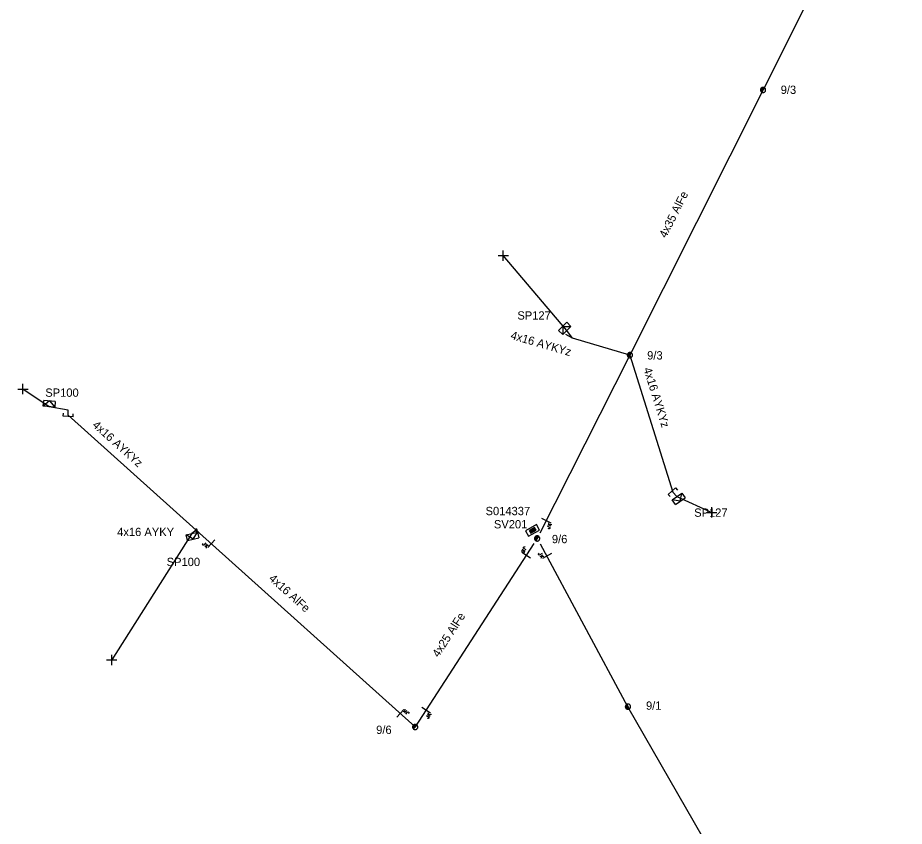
# Model space of a CAD drawing. Extents: x -717562 to -713845, y -1151196 to -1143903.
# Drawn here: x -714702.4 to -714595.8, y -1145677.8 to -1145580.5 of the extents above; entities that cross this region are included whole.
import ezdxf

# ---------------------------------------------------------------- set-up
doc = ezdxf.new("R2010")
doc.units = 0
for name, color, linetype in [('Vrstva 1', 7, 'Continuous'), ('Vrstva 12', 7, 'Continuous'), ('Vrstva 13', 7, 'Continuous'), ('Vrstva 15', 7, 'Continuous'), ('Vrstva 18', 7, 'Continuous'), ('Vrstva 2', 7, 'Continuous'), ('Vrstva 28', 7, 'Continuous'), ('Vrstva 29', 7, 'Continuous'), ('Vrstva 30', 7, 'Continuous'), ('Vrstva 31', 7, 'Continuous'), ('Vrstva 33', 7, 'Continuous'), ('Vrstva 34', 7, 'Continuous'), ('Vrstva 52', 7, 'Continuous'), ('Vrstva 54', 7, 'Continuous'), ('Vrstva 55', 7, 'Continuous'), ('Vrstva 59', 7, 'Continuous'), ('Vrstva 8', 7, 'Continuous'), ('Vrstva 9', 7, 'Continuous')]:
    doc.layers.add(name, color=color, linetype=linetype)

# ---------------------------------------------------------------- blocks, each defined once
blk = doc.blocks.new('NN440')
at = {"layer": 'Vrstva 2'}
for points in [[(0.63, 0), (0.63, 0.06), (0.62, 0.13), (0.6, 0.19), (0.58, 0.25), (0.55, 0.31), (0.51, 0.37), (0.47, 0.42), (0.42, 0.46), (0.37, 0.51), (0.32, 0.54), (0.26, 0.57), (0.2, 0.59), (0.13, 0.61), (0.07, 0.62), (0, 0.63), (-0.06, 0.62), (-0.13, 0.61), (-0.19, 0.59), (-0.26, 0.57), (-0.31, 0.54), (-0.37, 0.51), (-0.42, 0.46), (-0.47, 0.42), (-0.51, 0.37), (-0.54, 0.31), (-0.57, 0.25), (-0.6, 0.19), (-0.62, 0.13), (-0.63, 0.06), (-0.63, 0), (-0.63, -0.07), (-0.62, -0.14), (-0.6, -0.2), (-0.57, -0.26), (-0.54, -0.32), (-0.51, -0.37), (-0.47, -0.43), (-0.42, -0.47), (-0.37, -0.51), (-0.31, -0.55), (-0.26, -0.58), (-0.19, -0.6), (-0.13, -0.62), (-0.06, -0.63), (0, -0.63), (0.07, -0.63), (0.13, -0.62), (0.2, -0.6), (0.26, -0.58), (0.32, -0.55), (0.37, -0.51), (0.42, -0.47), (0.47, -0.43), (0.51, -0.37), (0.55, -0.32), (0.58, -0.26), (0.6, -0.2), (0.62, -0.14), (0.63, -0.07), (0.63, 0)], [(-0.63, 0), (0.63, 0)], [(-0.6, -0.18), (0.57, -0.18)], [(-0.51, -0.32), (0.5, -0.32)], [(-0.37, -0.47), (0.35, -0.47)]]:
    blk.add_lwpolyline(points, dxfattribs=at)
blk = doc.blocks.new('NN840')
at = {"layer": 'Vrstva 15'}
for points in [[(0, 0.62), (0, -0.63)], [(-0.75, -0.71), (-0.75, -0.66)], [(-0.73, -0.76), (-0.75, -0.71)], [(-0.66, -0.8), (-0.73, -0.76)], [(-0.63, -0.8), (-0.66, -0.8)], [(-0.56, -0.76), (-0.63, -0.8)], [(-0.54, -0.71), (-0.56, -0.76)], [(-0.54, -0.38), (-0.54, -0.71)], [(-0.33, -0.38), (-0.33, -0.8)], [(-0.33, -0.64), (-0.13, -0.38)], [(-0.26, -0.56), (-0.09, -0.8)]]:
    blk.add_lwpolyline(points, dxfattribs=at)
blk = doc.blocks.new('NN800')
at = {"layer": 'Vrstva 1'}
for points in [[(-0.44, 0.44), (0.44, -0.44)], [(-0.44, -0.44), (0.44, 0.44)]]:
    blk.add_lwpolyline(points, dxfattribs=at)
blk = doc.blocks.new('NN620')
at = {"layer": 'Vrstva 8'}
for points in [[(0.75, 0), (-0.75, 0)], [(-0.75, 0), (-0.75, -0.75)], [(0.75, -0.75), (0.75, 0)], [(-0.75, -0.75), (0.75, -0.75)], [(0.37, -0.18), (-0.38, -0.18)], [(-0.38, -0.18), (-0.38, -0.56)], [(-0.38, -0.56), (0.37, -0.56)], [(0.32, -0.23), (-0.33, -0.23)], [(-0.33, -0.23), (-0.33, -0.51)], [(-0.33, -0.51), (0.32, -0.51)], [(0.27, -0.27), (-0.28, -0.27)], [(-0.28, -0.27), (-0.28, -0.46)], [(-0.28, -0.46), (0.27, -0.46)], [(0.23, -0.32), (-0.23, -0.32)], [(-0.23, -0.32), (-0.23, -0.42)], [(-0.23, -0.42), (0.23, -0.42)], [(-0.19, -0.37), (0.19, -0.37)], [(0.23, -0.42), (0.23, -0.32)], [(0.27, -0.46), (0.27, -0.27)], [(0.32, -0.51), (0.32, -0.23)], [(0.37, -0.56), (0.37, -0.18)]]:
    blk.add_lwpolyline(points, dxfattribs=at)
blk = doc.blocks.new('NN630')
at = {"layer": 'Vrstva 9'}
for points in [[(0, -0.7), (-0.7, 0)], [(-0.7, -0.7), (-0.7, 0), (0.7, 0), (0.7, -0.7)], [(-0.7, -0.7), (0.7, -0.7)], [(0, -0.7), (0.7, 0)]]:
    blk.add_lwpolyline(points, dxfattribs=at)
blk = doc.blocks.new('NN500')
at = {"layer": 'Vrstva 2'}
for points in [[(0, -0.24), (0.02, -0.23), (0.05, -0.23), (0.07, -0.22), (0.09, -0.22), (0.12, -0.2), (0.14, -0.19), (0.16, -0.18), (0.17, -0.16), (0.19, -0.14), (0.2, -0.12), (0.21, -0.1), (0.22, -0.07), (0.23, -0.05), (0.23, -0.02), (0.23, 0), (0.23, 0.02), (0.23, 0.05), (0.22, 0.07), (0.21, 0.1), (0.2, 0.12), (0.19, 0.14), (0.17, 0.16), (0.16, 0.17), (0.14, 0.19), (0.12, 0.2), (0.09, 0.21), (0.07, 0.22), (0.05, 0.23), (0.02, 0.23), (0, 0.23), (-0.03, 0.23), (-0.05, 0.23), (-0.07, 0.22), (-0.1, 0.21), (-0.12, 0.2), (-0.14, 0.19), (-0.16, 0.17), (-0.18, 0.16), (-0.19, 0.14), (-0.2, 0.12), (-0.22, 0.1), (-0.22, 0.07), (-0.23, 0.05), (-0.23, 0.02), (-0.24, 0), (-0.23, -0.02), (-0.23, -0.05), (-0.22, -0.07), (-0.22, -0.1), (-0.2, -0.12), (-0.19, -0.14), (-0.18, -0.16), (-0.16, -0.18), (-0.14, -0.19), (-0.12, -0.2), (-0.1, -0.22), (-0.07, -0.22), (-0.05, -0.23), (-0.03, -0.23), (0, -0.24)], [(0, -0.24), (0.02, -0.23), (0.05, -0.23), (0.07, -0.22), (0.09, -0.22), (0.12, -0.2), (0.14, -0.19), (0.16, -0.18), (0.17, -0.16), (0.19, -0.14), (0.2, -0.12), (0.21, -0.1), (0.22, -0.07), (0.23, -0.05), (0.23, -0.02), (0.23, 0), (0.23, 0.02), (0.23, 0.05), (0.22, 0.07), (0.21, 0.1), (0.2, 0.12), (0.19, 0.14), (0.17, 0.16), (0.16, 0.17), (0.14, 0.19), (0.12, 0.2), (0.09, 0.21), (0.07, 0.22), (0.05, 0.23), (0.02, 0.23), (0, 0.23), (-0.03, 0.23), (-0.05, 0.23), (-0.07, 0.22), (-0.1, 0.21), (-0.12, 0.2), (-0.14, 0.19), (-0.16, 0.17), (-0.18, 0.16), (-0.19, 0.14), (-0.2, 0.12), (-0.22, 0.1), (-0.22, 0.07), (-0.23, 0.05), (-0.23, 0.02), (-0.24, 0), (-0.23, -0.02), (-0.23, -0.05), (-0.22, -0.07), (-0.22, -0.1), (-0.2, -0.12), (-0.19, -0.14), (-0.18, -0.16), (-0.16, -0.18), (-0.14, -0.19), (-0.12, -0.2), (-0.1, -0.22), (-0.07, -0.22), (-0.05, -0.23), (-0.03, -0.23), (0, -0.24)], [(0, -0.21), (0.02, -0.2), (0.04, -0.2), (0.06, -0.2), (0.08, -0.19), (0.1, -0.18), (0.12, -0.17), (0.14, -0.15), (0.15, -0.14), (0.16, -0.12), (0.18, -0.1), (0.19, -0.08), (0.19, -0.06), (0.2, -0.04), (0.2, -0.02), (0.2, 0), (0.2, 0.02), (0.2, 0.04), (0.19, 0.06), (0.19, 0.08), (0.18, 0.1), (0.16, 0.12), (0.15, 0.14), (0.14, 0.15), (0.12, 0.17), (0.1, 0.18), (0.08, 0.19), (0.06, 0.19), (0.04, 0.2), (0.02, 0.2), (0, 0.2), (-0.02, 0.2), (-0.04, 0.2), (-0.06, 0.19), (-0.08, 0.19), (-0.1, 0.18), (-0.12, 0.17), (-0.14, 0.15), (-0.15, 0.14), (-0.17, 0.12), (-0.18, 0.1), (-0.19, 0.08), (-0.2, 0.06), (-0.2, 0.04), (-0.21, 0.02), (-0.21, 0), (-0.21, -0.02), (-0.2, -0.04), (-0.2, -0.06), (-0.19, -0.08), (-0.18, -0.1), (-0.17, -0.12), (-0.15, -0.14), (-0.14, -0.15), (-0.12, -0.17), (-0.1, -0.18), (-0.08, -0.19), (-0.06, -0.2), (-0.04, -0.2), (-0.02, -0.2), (0, -0.21)], [(0, -0.18), (0.02, -0.18), (0.04, -0.17), (0.05, -0.17), (0.07, -0.16), (0.09, -0.15), (0.1, -0.14), (0.12, -0.13), (0.13, -0.12), (0.14, -0.1), (0.15, -0.09), (0.16, -0.07), (0.17, -0.05), (0.17, -0.04), (0.17, -0.02), (0.17, 0), (0.17, 0.02), (0.17, 0.04), (0.17, 0.05), (0.16, 0.07), (0.15, 0.09), (0.14, 0.1), (0.13, 0.12), (0.12, 0.13), (0.1, 0.14), (0.09, 0.15), (0.07, 0.16), (0.05, 0.17), (0.04, 0.17), (0.02, 0.17), (0, 0.18), (-0.02, 0.17), (-0.04, 0.17), (-0.06, 0.17), (-0.07, 0.16), (-0.09, 0.15), (-0.1, 0.14), (-0.12, 0.13), (-0.13, 0.12), (-0.14, 0.1), (-0.15, 0.09), (-0.16, 0.07), (-0.17, 0.05), (-0.17, 0.04), (-0.18, 0.02), (-0.18, 0), (-0.18, -0.02), (-0.17, -0.04), (-0.17, -0.05), (-0.16, -0.07), (-0.15, -0.09), (-0.14, -0.1), (-0.13, -0.12), (-0.12, -0.13), (-0.1, -0.14), (-0.09, -0.15), (-0.07, -0.16), (-0.06, -0.17), (-0.04, -0.17), (-0.02, -0.18), (0, -0.18)], [(0, -0.15), (0.01, -0.15), (0.03, -0.14), (0.04, -0.14), (0.06, -0.13), (0.07, -0.13), (0.08, -0.12), (0.1, -0.11), (0.11, -0.1), (0.12, -0.09), (0.13, -0.07), (0.13, -0.06), (0.14, -0.05), (0.14, -0.03), (0.14, -0.02), (0.14, 0), (0.14, 0.01), (0.14, 0.03), (0.14, 0.04), (0.13, 0.06), (0.13, 0.07), (0.12, 0.09), (0.11, 0.1), (0.1, 0.11), (0.08, 0.12), (0.07, 0.13), (0.06, 0.13), (0.04, 0.14), (0.03, 0.14), (0.01, 0.14), (0, 0.15), (-0.02, 0.14), (-0.03, 0.14), (-0.05, 0.14), (-0.06, 0.13), (-0.07, 0.13), (-0.09, 0.12), (-0.1, 0.11), (-0.11, 0.1), (-0.12, 0.09), (-0.13, 0.07), (-0.13, 0.06), (-0.14, 0.04), (-0.14, 0.03), (-0.15, 0.01), (-0.15, 0), (-0.15, -0.02), (-0.14, -0.03), (-0.14, -0.05), (-0.13, -0.06), (-0.13, -0.07), (-0.12, -0.09), (-0.11, -0.1), (-0.1, -0.11), (-0.09, -0.12), (-0.07, -0.13), (-0.06, -0.13), (-0.05, -0.14), (-0.03, -0.14), (-0.02, -0.15), (0, -0.15)], [(0, -0.12), (0.01, -0.12), (0.02, -0.11), (0.03, -0.11), (0.05, -0.11), (0.06, -0.1), (0.07, -0.09), (0.08, -0.09), (0.09, -0.08), (0.09, -0.07), (0.1, -0.06), (0.11, -0.05), (0.11, -0.04), (0.11, -0.02), (0.11, -0.01), (0.12, 0), (0.11, 0.01), (0.11, 0.02), (0.11, 0.04), (0.11, 0.05), (0.1, 0.06), (0.09, 0.07), (0.09, 0.08), (0.08, 0.09), (0.07, 0.09), (0.06, 0.1), (0.05, 0.11), (0.03, 0.11), (0.02, 0.11), (0.01, 0.12), (0, 0.12), (-0.01, 0.12), (-0.03, 0.11), (-0.04, 0.11), (-0.05, 0.11), (-0.06, 0.1), (-0.07, 0.09), (-0.08, 0.09), (-0.09, 0.08), (-0.1, 0.07), (-0.1, 0.06), (-0.11, 0.05), (-0.11, 0.04), (-0.12, 0.02), (-0.12, 0.01), (-0.12, 0), (-0.12, -0.01), (-0.12, -0.02), (-0.11, -0.04), (-0.11, -0.05), (-0.1, -0.06), (-0.1, -0.07), (-0.09, -0.08), (-0.08, -0.09), (-0.07, -0.09), (-0.06, -0.1), (-0.05, -0.11), (-0.04, -0.11), (-0.03, -0.11), (-0.01, -0.12), (0, -0.12)], [(0, -0.09), (0.01, -0.09), (0.02, -0.09), (0.03, -0.08), (0.03, -0.08), (0.04, -0.08), (0.05, -0.07), (0.06, -0.07), (0.06, -0.06), (0.07, -0.05), (0.07, -0.04), (0.08, -0.04), (0.08, -0.03), (0.08, -0.02), (0.09, -0.01), (0.09, 0), (0.09, 0.01), (0.08, 0.02), (0.08, 0.03), (0.08, 0.03), (0.07, 0.04), (0.07, 0.05), (0.06, 0.06), (0.06, 0.06), (0.05, 0.07), (0.04, 0.07), (0.03, 0.08), (0.03, 0.08), (0.02, 0.08), (0.01, 0.09), (0, 0.09), (-0.01, 0.09), (-0.02, 0.08), (-0.03, 0.08), (-0.04, 0.08), (-0.04, 0.07), (-0.05, 0.07), (-0.06, 0.06), (-0.07, 0.06), (-0.07, 0.05), (-0.08, 0.04), (-0.08, 0.03), (-0.08, 0.03), (-0.09, 0.02), (-0.09, 0.01), (-0.09, 0), (-0.09, -0.01), (-0.09, -0.02), (-0.08, -0.03), (-0.08, -0.04), (-0.08, -0.04), (-0.07, -0.05), (-0.07, -0.06), (-0.06, -0.07), (-0.05, -0.07), (-0.04, -0.08), (-0.04, -0.08), (-0.03, -0.08), (-0.02, -0.09), (-0.01, -0.09), (0, -0.09)], [(0, -0.06), (0, -0.06), (0.01, -0.06), (0.02, -0.05), (0.02, -0.05), (0.03, -0.05), (0.03, -0.05), (0.04, -0.04), (0.04, -0.04), (0.05, -0.03), (0.05, -0.03), (0.05, -0.02), (0.05, -0.02), (0.05, -0.01), (0.06, -0.01), (0.06, 0), (0.06, 0.01), (0.05, 0.01), (0.05, 0.02), (0.05, 0.02), (0.05, 0.03), (0.05, 0.03), (0.04, 0.04), (0.04, 0.04), (0.03, 0.05), (0.03, 0.05), (0.02, 0.05), (0.02, 0.05), (0.01, 0.06), (0, 0.06), (0, 0.06), (-0.01, 0.06), (-0.01, 0.06), (-0.02, 0.05), (-0.02, 0.05), (-0.03, 0.05), (-0.03, 0.05), (-0.04, 0.04), (-0.04, 0.04), (-0.05, 0.03), (-0.05, 0.03), (-0.05, 0.02), (-0.06, 0.02), (-0.06, 0.01), (-0.06, 0.01), (-0.06, 0), (-0.06, -0.01), (-0.06, -0.01), (-0.06, -0.02), (-0.05, -0.02), (-0.05, -0.03), (-0.05, -0.03), (-0.04, -0.04), (-0.04, -0.04), (-0.03, -0.05), (-0.03, -0.05), (-0.02, -0.05), (-0.02, -0.05), (-0.01, -0.06), (-0.01, -0.06), (0, -0.06)], [(0, -0.03), (0, -0.03), (0, -0.03), (0.01, -0.03), (0.01, -0.03), (0.01, -0.02), (0.02, -0.02), (0.02, -0.02), (0.02, -0.02), (0.02, -0.02), (0.02, -0.01), (0.02, -0.01), (0.03, -0.01), (0.03, -0.01), (0.03, 0), (0.03, 0), (0.03, 0), (0.03, 0.01), (0.03, 0.01), (0.02, 0.01), (0.02, 0.01), (0.02, 0.02), (0.02, 0.02), (0.02, 0.02), (0.02, 0.02), (0.01, 0.02), (0.01, 0.02), (0.01, 0.03), (0, 0.03), (0, 0.03), (0, 0.03), (0, 0.03), (-0.01, 0.03), (-0.01, 0.03), (-0.01, 0.02), (-0.02, 0.02), (-0.02, 0.02), (-0.02, 0.02), (-0.02, 0.02), (-0.02, 0.02), (-0.03, 0.01), (-0.03, 0.01), (-0.03, 0.01), (-0.03, 0.01), (-0.03, 0), (-0.03, 0), (-0.03, 0), (-0.03, -0.01), (-0.03, -0.01), (-0.03, -0.01), (-0.03, -0.01), (-0.02, -0.02), (-0.02, -0.02), (-0.02, -0.02), (-0.02, -0.02), (-0.02, -0.02), (-0.01, -0.03), (-0.01, -0.03), (-0.01, -0.03), (0, -0.03), (0, -0.03)], [(0.23, 0), (0.7, 0)]]:
    blk.add_lwpolyline(points, dxfattribs=at)
blk = doc.blocks.new('NN510')
at = {"layer": 'Vrstva 2'}
blk.add_lwpolyline([(0, 0), (0, 0.94)], dxfattribs=at)
blk = doc.blocks.new('NN515')
at = {"layer": 'Vrstva 2'}
for points in [[(-0.59, 0.18), (0.59, 0.18)], [(-0.59, 0.18), (-0.59, -0.18)], [(0.59, 0.18), (0.59, -0.18)]]:
    blk.add_lwpolyline(points, dxfattribs=at)

msp = doc.modelspace()

# ---------------------------------------------------------------- linework, layer by layer
at = {"layer": 'Vrstva 1'}
for points in [[(-714598.13, -1145559.99), (-714612.77, -1145589.2), (-714628.77, -1145621.09), (-714639.6, -1145642.51)], [(-714654.58, -1145665.81), (-714680.89, -1145642.14)], [(-714640.32, -1145643.76), (-714654.58, -1145665.81)], [(-714556.65, -1145780.38), (-714574.01, -1145752.25), (-714595.01, -1145718.48), (-714616.99, -1145684.31), (-714629.01, -1145663.37), (-714639.53, -1145643.84)]]:
    msp.add_lwpolyline(points, dxfattribs=at)
at = {"layer": 'Vrstva 52'}
msp.add_lwpolyline([(-714680.89, -1145642.14), (-714681.43, -1145642.54)], dxfattribs=at)
at = {"layer": 'Vrstva 54'}
for points in [[(-714628.77, -1145621.09), (-714635.67, -1145619.07), (-714636.36, -1145618.13)], [(-714628.77, -1145621.09), (-714623.62, -1145637.59), (-714623.12, -1145638.09)], [(-714680.89, -1145642.14), (-714696.28, -1145628.3), (-714696.29, -1145627.72), (-714698.59, -1145627.3)]]:
    msp.add_lwpolyline(points, dxfattribs=at)
at = {"layer": 'Vrstva 59'}
for points in [[(-714636.36, -1145618.13), (-714644, -1145609.13)], [(-714698.59, -1145627.3), (-714701.73, -1145625.18)], [(-714623.12, -1145638.09), (-714618.94, -1145640)], [(-714681.43, -1145642.54), (-714691.06, -1145657.75)]]:
    msp.add_lwpolyline(points, dxfattribs=at)

# ---------------------------------------------------------------- block references
at = {"layer": 'Vrstva 13'}
for name, p, xscale, yscale, rotation in [('NN440', (-714612.77, -1145589.2), 0.5, 0.5, -116.631238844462), ('NN440', (-714628.77, -1145621.09), 0.49999999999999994, 0.5000000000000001, -116.63123890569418), ('NN500', (-714680.89, -1145642.14), 0.5, 0.5, -41.97100004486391), ('NN440', (-714639.92, -1145643.14), 0.5, 0.5, -122.8866972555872), ('NN440', (-714629.01, -1145663.37), 0.5, 0.5000000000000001, -61.06082495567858), ('NN440', (-714654.58, -1145665.81), 0.5, 0.5, -131.97050271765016)]:
    msp.add_blockref(name, p, dxfattribs=dict(at, xscale=xscale, yscale=yscale, rotation=rotation))
for name, p, rotation in [('NN510', (-714635.67, -1145619.07), 60.72533888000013), ('NN515', (-714696.28, -1145628.3), 176.23146938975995), ('NN515', (-714623.62, -1145637.59), 40.66173333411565)]:
    msp.add_blockref(name, p, dxfattribs=dict(at, rotation=rotation))
at = {"layer": 'Vrstva 18'}
for p, rotation in [((-714638.83, -1145640.98), 63.17055563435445), ((-714679.09, -1145643.76), -41.970969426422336), ((-714641.23, -1145645.18), -122.8864805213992), ((-714638.73, -1145645.25), -60.700836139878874), ((-714656.38, -1145664.19), 138.0290305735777), ((-714656.38, -1145664.19), 138.0290305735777), ((-714653.26, -1145663.78), 57.11351942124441)]:
    msp.add_blockref('NN840', p, dxfattribs=dict(at, rotation=rotation))
at = {"layer": 'Vrstva 28', "rotation": -150.70100008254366}
msp.add_blockref('NN620', (-714640.29, -1145642.49), dxfattribs=at)
at = {"layer": 'Vrstva 31'}
for p, rotation in [((-714636.36, -1145618.13), -134.96786668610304), ((-714698.59, -1145627.3), 175.56352490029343), ((-714623.12, -1145638.09), 35.21462504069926), ((-714681.43, -1145642.54), 13.41458882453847)]:
    msp.add_blockref('NN630', p, dxfattribs=dict(at, rotation=rotation))
at = {"layer": 'Vrstva 34'}
for p, rotation in [((-714644, -1145609.13), 45), ((-714701.73, -1145625.18), 44.99999995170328), ((-714618.94, -1145640), 44.99999995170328), ((-714691.06, -1145657.75), 45)]:
    msp.add_blockref('NN800', p, dxfattribs=dict(at, rotation=rotation))

# ---------------------------------------------------------------- texts
at = {"layer": 'Vrstva 12'}
for s, p in [('9/3', (-714610.65, -1145589.68)), ('9/3', (-714626.7, -1145621.62)), ('9/6', (-714638.15, -1145643.71)), ('9/1', (-714626.84, -1145663.74)), ('9/6', (-714659.27, -1145666.65))]:
    msp.add_text(s, height=1, dxfattribs=at).set_placement(p)
at = {"layer": 'Vrstva 2'}
for s, rotation, p in [('4x35 AlFe', 63.368, (-714624.43, -1145607.08)), ('4x16 AlFe', 318.029, (-714672.25, -1145648.07)), ('4x25 AlFe', 57.114, (-714651.78, -1145657.52))]:
    msp.add_text(s, height=1, rotation=rotation, dxfattribs=at).set_placement(p)
at = {"layer": 'Vrstva 29'}
msp.add_text('S014337', height=1, rotation=0.014, dxfattribs=at).set_placement((-714646.12, -1145640.34))
at = {"layer": 'Vrstva 30'}
msp.add_text('SV201', height=1, rotation=0.009, dxfattribs=at).set_placement((-714645.12, -1145641.93))
at = {"layer": 'Vrstva 33'}
for s, p in [('SP127', (-714642.3, -1145616.82)), ('SP100', (-714699.04, -1145626.1)), ('SP127', (-714621.05, -1145640.53)), ('SP100', (-714684.45, -1145646.46))]:
    msp.add_text(s, height=1, dxfattribs=at).set_placement(p)
at = {"layer": 'Vrstva 54'}
msp.add_text('4x16 AYKY', height=1, dxfattribs=at).set_placement((-714690.4, -1145642.85))
at = {"layer": 'Vrstva 55'}
for rotation, p in [(343.719, (-714643.19, -1145619.12)), (287.31, (-714627.16, -1145622.74)), (318.031, (-714693.46, -1145629.62))]:
    msp.add_text('4x16 AYKYz', height=1, rotation=rotation, dxfattribs=at).set_placement(p)

doc.saveas('drawing.dxf')
